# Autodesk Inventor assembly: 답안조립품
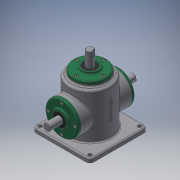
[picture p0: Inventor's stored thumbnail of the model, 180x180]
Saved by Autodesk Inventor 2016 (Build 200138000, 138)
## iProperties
Created: 2019-08
Part Number: 답안조립품
Material: 일반
Document SubType Name: Assembly
Designer: user
Author: user
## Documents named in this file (16)
- D:\490823V1005\답안조립품.iam
- D:\490823V1005\메인 베벨기어.ipt
- D:\490823V1005\메인 축.ipt
- 메인 축.ipt
- D:\490823V1005\베어링 6203.ipt
- D:\490823V1005\본체.ipt
- D:\490823V1005\볼트 M4.ipt
- 볼트 M4.ipt
- D:\490823V1005\서브 베벨기어.ipt
- D:\490823V1005\서브 축.ipt
- 서브 축.ipt
- D:\490823V1005\오일 실.ipt
- 오일 실.ipt
- D:\490823V1005\커버.ipt
- D:\490823V1005\키 4x4.ipt
- D:\490823V1005\키 5x5.ipt
